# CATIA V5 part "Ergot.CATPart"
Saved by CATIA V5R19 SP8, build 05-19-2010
Part number: Ergot
Bounding box of the stored display mesh (mm): x -21.5 to -18.5, y 12.5 to 15.5, z -5 to 5
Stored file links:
  C:\Users\ThinkMotion\Desktop\EU_thinkMotion\iao\IAO_MMS_Groupe3\ecartoux\projet_IAO_ecartoux\projet_IAO_ecartoux\griffe_d'une_camera_ecartoux\Ergot.CATPart
  C:\Users\ThinkMotion\Desktop\EU_thinkMotion\iao\IAO_MMS_Groupe3\ecartoux\projet_IAO_ecartoux\projet_IAO_ecartoux\griffe_d'une_camera_ecartoux\Mecanisme_a_coulisse_et_leviers_de_la_griffe_d'un_camera_ecartoux.CATProduct
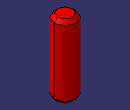
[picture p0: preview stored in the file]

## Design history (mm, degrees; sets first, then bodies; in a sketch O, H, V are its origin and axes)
Set1
  Sketch1, origin (0, 0, 0), H (1, 0, 0), V (0, 1, 0), geometry linked from another document
Body1 (main body)
  Pad1: profile Sketch1, direction (0, 0, 1), length 5, mirrored extent
  Chamfer1: length 0.5, angle 45, on edge [start face of Pad1 | face of Pad1]; edge [face of Pad1 | end face of Pad1]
